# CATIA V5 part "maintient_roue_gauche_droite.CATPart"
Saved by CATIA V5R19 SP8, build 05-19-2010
Part number: maintient_roue_gauche_droite
Bounding box of the stored display mesh (mm): x -825 to 825, y 445.52 to 1158.02, z -781.846 to -308.53
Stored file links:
  G:\EU_thinkMotion\CFAO_2010\MMS_groupe2\MMS_groupe2\OK\mmartini\mmartiniCFAO\maintient_roue_gauche_droite.CATPart
  C:\Users\Mathieu Martini\Desktop\CFAO\Animation\CFAO.CATProduct
  G:\EU_thinkMotion\CFAO_2010\MMS_groupe2\MMS_groupe2\OK\mmartini\mmartiniCFAO\Squelette.CATPart
  G:\EU_thinkMotion\CFAO_2010\MMS_groupe2\MMS_groupe2\OK\mmartini\mmartiniCFAO\Jambe_gauche_roue.CATPart
  G:\EU_thinkMotion\CFAO_2010\MMS_groupe2\MMS_groupe2\OK\mmartini\mmartiniCFAO\jambe_roue_droite.CATPart
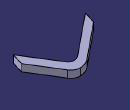
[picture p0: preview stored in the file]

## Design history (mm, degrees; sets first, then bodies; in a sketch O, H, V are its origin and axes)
Parameters
  LENGTH = 150 mm
  LENGTH = 120 mm
External parameters (linked from other documents)
  External.diametre_canon = 150 mm
AxisSystem1: origin (0, 0, 0), X (1, 0, 0), Y (0, 1, 0), Z (0, 0, 1)
Set1
  Sketch1 on Plane1, origin (0, 0, -368.7113), H (1, 0, 0), V (0, 1, 0)
    arc A1 centre (0, 783.02) radius 375 from (225, 1083.02) to (0, 1158.02) ccw
    point P1 (0, 783.02)
    reference projected point E1 (0, 783.02) from Point1
    line L1 (225, 1083.02) -> (825, 633.02)
    point P2 (225, 1083.02)
    point P3 (825, 633.02)
    axis line L2 (0, 344.6948) -> (0, 1215.9798)
    point P5 (0, 1215.9798)
    reference projected point E2 (0, 783.02) from Point2
    arc A2 centre (0, 783.02) radius 225 from (135, 963.02) to (0, 1008.02) ccw
    reference intersected line E3 through (825, 0) direction (0, 1) from Plane2
    reference projected point E4 (0, 783.02) from Point2
    point P6 (0, 1158.02)
    point P7 (0, 1008.02)
    line L3 (135, 963.02) -> (825, 445.52)
    point P8 (135, 963.02)
    point P9 (825, 445.52)
    reference intersected line E5 through (825, 0) direction (0, 1) from Plane2
    line L4 (825, 633.02) -> (825, 445.52)
    point P11 (-225, 1083.02)
    point P12 (-825, 633.02)
    point P13 (0, 1215.9798)
    point P14 (0, 1158.02)
    point P15 (0, 1008.02)
    point P16 (-135, 963.02)
    point P17 (-825, 445.52)
    arc A3 centre (0, 783.02) radius 375 from (-225, 1083.02) to (0, 1158.02) cw
    line L5 (-225, 1083.02) -> (-825, 633.02)
    arc A4 centre (0, 783.02) radius 225 from (-135, 963.02) to (0, 1008.02) cw
    line L6 (-135, 963.02) -> (-825, 445.52)
    line L7 (-825, 633.02) -> (-825, 445.52)
    radius A1 = 375 {= External.diametre_canon *2.5}
    distance A2 A1 = 150 {= External.diametre_canon}
    distance E4 P3 V = 150 {= External.diametre_canon}
    coincidence: P1 E1, E2 L2, P3 E3, L2 P6, L2 P7, P9 E5, P6 P14, P7 P15
    tangency: L1 A1, L3 A2
    vertical: L2 V, L4 V
    parallelism: L3 L1
    symmetry: P2 P11 L2, P3 P12 L2, P5 P13 L2, P6 P14 L2, P7 P15 L2, P8 P16 L2, P9 P17 L2, A1 A3 L2, L1 L5 L2, A2 A4 L2, L3 L6 L2, L4 L7 L2
  Sketch2 on Plane4, origin (0, 783.02, -443.7113), H (1, 0, 0), V (0, 0.493, 0.87)
    line L1 (825, -11) -> (-825, -11)
    line L2 (-825, -11) -> (-825, -161)
    line L3 (-825, -161) -> (825, -161)
    line L4 (825, -161) -> (825, -11)
    reference intersected line E1 through (825, 0) direction (0, 1) from Plane2
    reference intersected line E2 through (-825, 0) direction (0, 1) from Plane5
    reference projected point E3 (0, 0) from Point2
    distance L1 L3 = 150 {= External.diametre_canon}
    distance E3 L1 = 11 {= External.diametre_canon *0.07333333}
    horizontal: L1 H, L3 H
    vertical: L2 V, L4 V
    coincidence: L4 E1, L2 E2
Set2
  Plane1: linked copy from another document
  Point1: linked copy from another document
  Point2: linked copy from another document
  Plane2 "Plan_jambe_droite_roue": linked copy from another document
  Plane3: linked copy from another document
  Plane4: linked copy from another document
  Plane5 "Plan_jambe_gauche_roue": linked copy from another document
  DatumCurve1: linked copy from another document
  Line1: linked copy from another document
  DatumCurve2: linked copy from another document
Body1 (main body)
  SolidCombine1: FirstComponentProfile Sketch1, FirstComponentDirection Sketch1, SecondComponentProfile Sketch2, SecondComponentDirection edge of DatumCurve2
